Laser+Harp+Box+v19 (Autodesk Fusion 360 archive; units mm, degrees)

design "Laser Harp Box" references "US-100 Sonar Sensor with Jumper STEP"
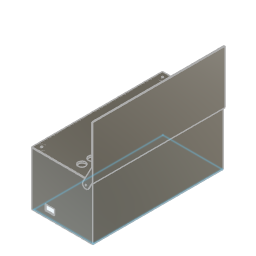
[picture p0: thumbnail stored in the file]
parameter "inner_length" = 290
parameter "inner_width" = 133
parameter "enclosure_height" = 120
parameter "screw_holder" = 9
parameter "screw_hole" = 3.8
parameter "base_height" = 13
parameter "base_plate_fastener_height" = 14.5
parameter "top_plate_fastener_height" = 14.5
parameter "top_height" = 2
parameter "wall_thickness" = 2
parameter "arduino_inputs_height" = 15
parameter "arduino_inputs_width" = 107
parameter "power_input_height" = 13
parameter "power_input_width" = 21
parameter "ultrasonic_sensor_diameter" = 16
parameter "ultrasonic_sensors_space" = 22.9
parameter "ultrasonic_space_to_side" = 22
parameter "ultrasonic_space_to_bottom" = 47
sketch "Sketch1" plane through (0, 0, 0) normal (0, 0, 1) x axis (1, 0, 0)
  line L1 (-66.5, -145) -> (66.5, -145)
  line L2 (-66.5, 145) -> (-66.5, -145)
  line L3 (66.5, 145) -> (-66.5, 145)
  line L4 (66.5, -145) -> (66.5, 145)
  line L5 (-66.5, 145) -> (66.5, -145)
  line L6 (66.5, 145) -> (-66.5, -145)
  line L7 (68.5, -147) -> (68.5, 147)
  line L8 (-68.5, -147) -> (68.5, -147)
  line L9 (-68.5, 147) -> (-68.5, -147)
  line L10 (68.5, 147) -> (-68.5, 147)
  circle C1 centre (-57.5, 136) radius 9
  circle C2 centre (-57.5, 136) radius 1.9
  circle C3 centre (-57.5, -136) radius 9
  circle C4 centre (-57.5, -136) radius 1.9
  circle C5 centre (57.5, -136) radius 9
  circle C6 centre (57.5, -136) radius 1.9
  circle C7 centre (57.5, 136) radius 9
  circle C8 centre (57.5, 136) radius 1.9
  point P6 (0, 0)
  point P1 (0, 0)
  point P4 (-66.5, 145)
  point P5 (66.5, 145)
  point P3 (-66.5, -145)
  horizontal L1
  perpendicular L1 L2
  parallel L1 L3
  parallel L2 L4
  coincident L5 P6
  coincident L6 P6
  coincident P1 P6
  tangent L2 C1
  tangent L3 C1
  concentric C1 C2
  tangent L2 C3
  tangent L1 C3
  concentric C3 C4
  tangent L1 C5
  tangent L4 C5
  concentric C5 C6
  tangent L3 C7
  tangent L4 C7
  concentric C7 C8
  dimension "d1" distance P4 P5 = 133 (= "inner_width")
  dimension "d2" distance P3 P4 = 290 (= "inner_length")
  dimension "d7" radius C1 = 9 (= "screw_holder")
  dimension "d8" diameter C2 = 3.8 (= "screw_hole")
  dimension "d11" radius C3 = 9 (= "screw_holder")
  dimension "d12" diameter C4 = 3.8 (= "screw_hole")
  dimension "d13" radius C5 = 9 (= "screw_holder")
  dimension "d14" diameter C6 = 3.8 (= "screw_hole")
  dimension "d15" radius C7 = 9 (= "screw_holder")
  dimension "d16" diameter C8 = 3.8 (= "screw_hole")
extrude "Extrude1" new body sketch "Sketch1" profile of L1 L2 L3 L4 L10 L9 L8 L7 along normal blind 120 (= "enclosure_height") bodies "Enclosure"
work_plane "WorkPlane1" AlongDistance 13 (= "base_height")
extrude "Extrude2" add sketch "Sketch1" profile of L1 L2 L3 L4 C1 C2 C3 C4 C5 C6 C7 C8 to an object from offset 13 (= "base_height")
work_plane "WorkPlane2" AlongDistance 0
sketch "Sketch3" plane through (0, 0, 120) normal (0, 0, 1) x axis (1, 0, 0)
  line L1 (57.5, 145) -> (-57.5, 145)
  line L2 (66.5, -136) -> (66.5, 136)
  line L3 (-57.5, -145) -> (57.5, -145)
  line L4 (-66.5, 136) -> (-66.5, -136)
  line L5 (-68.5, -147) -> (-68.5, 147)
  line L6 (68.5, -147) -> (-68.5, -147)
  line L7 (68.5, 147) -> (68.5, -147)
  line L8 (-68.5, 147) -> (68.5, 147)
  line L9 (-68.5, -147) -> (68.5, -147)
  line L10 (-68.5, 147) -> (-68.5, -147)
  line L11 (68.5, 147) -> (-68.5, 147)
  line L12 (68.5, -147) -> (68.5, 147)
  line L13 (-53.2574, -144.5) -> (53.2574, -144.5)
  line L14 (-66, 131.7574) -> (-66, -131.7574)
  line L15 (53.2574, 144.5) -> (-53.2574, 144.5)
  line L16 (66, -131.7574) -> (66, 131.7574)
  circle C1 centre (57.5, 136) radius 1.9
  circle C2 centre (-57.5, -136) radius 1.9
  circle C3 centre (57.5, -136) radius 1.9
  circle C4 centre (-57.5, 136) radius 1.9
  arc A1 centre (57.5, 136) radius 9 clockwise from (66.5, 136) to (57.5, 145)
  arc A2 centre (57.5, -136) radius 9 clockwise from (57.5, -145) to (66.5, -136)
  arc A3 centre (-57.5, -136) radius 9 clockwise from (-66.5, -136) to (-57.5, -145)
  arc A4 centre (-57.5, 136) radius 9 clockwise from (-57.5, 145) to (-66.5, 136)
  arc A5 centre (-57.5, -136) radius 9.5 clockwise from (-66, -131.7574) to (-53.2574, -144.5)
  arc A6 centre (-57.5, 136) radius 9.5 clockwise from (-53.2574, 144.5) to (-66, 131.7574)
  arc A7 centre (57.5, 136) radius 9.5 clockwise from (66, 131.7574) to (53.2574, 144.5)
  arc A8 centre (57.5, -136) radius 9.5 clockwise from (53.2574, -144.5) to (66, -131.7574)
  point P14 (-68.5, 147)
  point P20 (-68.5, 147)
  point P16 (68.5, -147)
  point P18 (68.5, -147)
  horizontal L9
  vertical L10
  horizontal L11
  vertical L12
  coincident P14 P20
  coincident P16 P18
  dimension "d34" = 0.5
extrude "Extrude4" new body sketch "Sketch3" along normal blind 2 (= "top_height") bodies "Lid"
extrude "Extrude5" new body sketch "Sketch3" profile of L1 A1 L2 A2 L3 A3 L4 A4 A8 A7 L15 A5 A6 L16 L14 L13 no distance stored
combine "Combine5"
extrude "Extrude6" add sketch "Sketch3" profile of A8 A7 L15 A5 A6 L16 L14 L13 no distance stored
sketch "Sketch6" plane through (0, 147, 0) normal (0, 1, 0) x axis (-1, 0, 0)
  line L1 (68.5, 0) -> (-68.5, 0)
  line L2 (68.5, 120) -> (68.5, 0)
  line L3 (-68.5, 120) -> (68.5, 120)
  line L4 (-68.5, 0) -> (-68.5, 120)
  line L5 (0, 13) -> (0, 0)
  line L6 (-53.5, 13) -> (53.5, 13)
  line L7 (-53.5, 28) -> (-53.5, 13)
  line L8 (53.5, 28) -> (-53.5, 28)
  line L9 (53.5, 13) -> (53.5, 28)
  point P1 (0, 0)
  point P6 (0, 0)
  point P7 (0, 13)
  point P8 (53.5, 13)
  point P9 (-53.5, 13)
  point P11 (53.5, 28)
  coincident P1 P6
  perpendicular L1 L5
  horizontal L6
  vertical L7
  horizontal L8
  vertical L9
  midpoint P7 L6
  dimension "d46" distance P6 P7 = 13 (= "base_height")
  dimension "d47" distance P8 P9 = 107 (= "arduino_inputs_width")
  dimension "d48" distance P8 P11 = 15 (= "arduino_inputs_height")
extrude "Extrude7" cut sketch "Sketch6" profile of L6 L7 L8 L9 against normal blind 30
sketch "Sketch7" plane through (0, -147, 0) normal (0, -1, 0) x axis (1, 0, 0)
  line L1 (68.5, 0) -> (-68.5, 0)
  line L2 (68.5, 120) -> (68.5, 0)
  line L3 (-68.5, 120) -> (68.5, 120)
  line L4 (-68.5, 0) -> (-68.5, 120)
  line L5 (-38.5, 13) -> (-68.5, 13)
  line L6 (-38.5, 0) -> (-38.5, 13)
  line L7 (-17.5, 13) -> (-38.5, 13)
  line L8 (-17.5, 26) -> (-17.5, 13)
  line L9 (-38.5, 26) -> (-17.5, 26)
  line L10 (-38.5, 13) -> (-38.5, 26)
  point P6 (-68.5, 13)
  point P7 (-38.5, 13)
  point P8 (-38.5, 0)
  point P9 (-17.5, 13)
  point P11 (-38.5, 26)
  coincident L4 P6
  perpendicular L4 L5
  perpendicular L1 L6
  horizontal L7
  vertical L8
  horizontal L9
  vertical L10
  dimension "d54" distance P6 P7 = 30
  dimension "d55" distance P7 P8 = 13 (= "base_height")
  dimension "d56" distance P7 P9 = 21 (= "power_input_width")
  dimension "d57" distance P7 P11 = 13 (= "power_input_height")
extrude "Extrude8" cut sketch "Sketch7" profile of L7 L8 L9 L10 against normal blind 15
sketch "Sketch8" plane through (0, 0, 122) normal (0, 0, 1) x axis (-1, 0, 0)
  line L1 (68.5, -147) -> (-68.5, -147)
  line L2 (68.5, 147) -> (68.5, -147)
  line L3 (-68.5, 147) -> (68.5, 147)
  line L4 (-68.5, -147) -> (-68.5, 147)
  line L5 (21.5, -45) -> (11.5, -45)
  line L6 (21.5, 45) -> (21.5, -45)
  line L7 (11.5, 45) -> (21.5, 45)
  line L8 (11.5, -45) -> (11.5, 45)
  line L9 (21.5, 45) -> (11.5, -45)
  line L10 (11.5, 45) -> (21.5, -45)
  line L11 (68.5, -147) -> (68.5, 147)
  line L12 (-68.5, -147) -> (68.5, -147)
  line L13 (-68.5, 147) -> (-68.5, -147)
  line L14 (-68.5, 0) -> (0, 0)
  line L15 (-4.8, 147) -> (-4.8, -147)
  circle C1 centre (57.5, -136) radius 1.9
  circle C2 centre (-57.5, -136) radius 1.9
  circle C3 centre (57.5, 136) radius 1.9
  circle C4 centre (-57.5, 136) radius 1.9
  circle C5 centre (-21.5, -102.1) radius 8
  circle C6 centre (-21.5, -125) radius 8
  circle C7 centre (-21.5, 125) radius 8
  circle C8 centre (-21.5, 102.1) radius 8
  circle C9 centre (-4.8, -82) radius 0.6
  circle C10 centre (-4.8, -79.4) radius 0.6
  circle C11 centre (-4.8, -32.4) radius 0.6
  circle C12 centre (-4.8, -29.8) radius 0.6
  circle C13 centre (-4.8, 32.4) radius 0.6
  circle C14 centre (-4.8, 29.8) radius 0.6
  circle C15 centre (-4.8, 82) radius 0.6
  circle C16 centre (-4.8, 79.4) radius 0.6
  point P14 (16.5, 0)
  point P1 (0, 0)
  point P21 (0, 0)
  point P22 (-68.5, 0)
  point P25 (-4.8, -147)
  point P26 (-4.8, 147)
  point P27 (-4.8, -82)
  point P28 (-4.8, -79.4)
  point P30 (-4.8, -32.4)
  point P29 (-4.8, -29.8)
  point P12 (21.5, 45)
  point P13 (11.5, 45)
  point P11 (21.5, -45)
  point P17 (-21.5, -102.1)
  point P18 (-21.5, -125)
  horizontal L5
  perpendicular L5 L6
  parallel L5 L7
  parallel L6 L8
  coincident L9 P14
  coincident L10 P14
  coincident P1 P21
  midpoint L13 P22
  symmetric C5 L14 C8
  symmetric C6 L14 C7
  coincident L1 P25
  coincident L3 P26
  perpendicular L3 L15
  coincident L15 P27
  coincident L15 P28
  coincident L15 P30
  coincident L15 P29
  symmetric L14 C9 C15
  symmetric L14 C10 C16
  symmetric L14 C11 C13
  symmetric L14 C12 C14
  dimension "d60" distance P12 P13 = 10
  dimension "d61" distance P11 P12 = 90
  dimension "d62" distance L6 L11 = 47
  dimension "d63" diameter C5 = 16 (= "ultrasonic_sensor_diameter")
  dimension "d64" diameter C6 = 16 (= "ultrasonic_sensor_diameter")
  dimension "d65" distance P17 P18 = 22.9 (= "ultrasonic_sensors_space")
  dimension "d66" distance P18 L12 = 22 (= "ultrasonic_space_to_side")
  dimension "d67" distance P17 L13 = 47 (= "ultrasonic_space_to_bottom")
  dimension "d88" distance L8 L15 = 16.3
  dimension "d89" diameter C9 = 1.2
  dimension "d90" diameter C10 = 1.2
  dimension "d91" distance P27 P28 = 2.6
  dimension "d92" distance P25 P27 = 65
  dimension "d93" diameter C11 = 1.2
  dimension "d94" diameter C12 = 1.2
  dimension "d95" distance P29 P30 = 2.6
  dimension "d96" distance P28 P30 = 47
extrude "Extrude9" cut sketch "Sketch8" profile of C1 C2 C3 C4 L5 L6 L7 L8 against normal blind 20
sketch "Sketch9" plane through (68.5, 0, 0) normal (1, 0, 0) x axis (0, 1, 0)
  line L1 (147, 0) -> (-147, 0)
  line L2 (147, 120) -> (147, 0)
  line L3 (-147, 120) -> (147, 120)
  line L4 (-147, 0) -> (-147, 120)
  line L5 (147, 120) -> (-147, 120)
  line L6 (147, 240) -> (147, 120)
  line L7 (-147, 240) -> (147, 240)
  line L8 (-147, 120) -> (-147, 240)
  point P5 (-147, 120)
  point P6 (-147, 120)
  point P9 (-147, 240)
  horizontal L5
  vertical L6
  horizontal L7
  vertical L8
  coincident P5 P6
  collinear L2 L6
  dimension "d74" distance P6 P9 = 120
extrude "Extrude10" new body sketch "Sketch9" profile of L3 L5 L6 L7 L8 along normal blind 2 bodies "Mirror Holder"
sketch "Sketch10" plane through (0, 147, 0) normal (0, 1, 0) x axis (-1, 0, 0)
  line L1 (-68.5, 240) -> (-68.5, 120)
  line L2 (-70.5, 240) -> (-68.5, 240)
  line L3 (-70.5, 120) -> (-70.5, 240)
  line L4 (-68.5, 120) -> (-70.5, 120)
  line L5 (-60.6488, 105.0663) -> (-68.5, 120)
  line L6 (-68.5, 151.6386) -> (-47.9407, 112.5332)
  line L7 (-68.5, 240) -> (-70.5, 240)
  line L8 (-68.5, 120) -> (-68.5, 240)
  line L9 (-70.5, 120) -> (-68.5, 120)
  line L10 (-70.5, 240) -> (-70.5, 120)
  circle C1 centre (-55, 110) radius 7.5
  circle C2 centre (-55, 110) radius 1.5
  point P2 (-68.5, 120)
  point P7 (-68.5, 120)
  point P8 (-60.6488, 105.0663)
  point P9 (-47.9407, 112.5332)
  point P10 (-68.5, 151.6386)
  point P4 (-70.5, 240)
  point P12 (-70.5, 240)
  coincident P2 P7
  coincident C1 P8
  coincident C1 P9
  coincident L1 P10
  parallel L5 L6
  concentric C1 C2
  horizontal L7
  vertical L8
  horizontal L9
  vertical L10
  coincident P4 P12
  dimension "d77" diameter C1 = 15
  dimension "d78" diameter C2 = 3
extrude "Extrude11" new body sketch "Sketch10" along normal blind 2
mirror "Mirror1" mirrorStitchTolerance 0.1
combine "Combine6"
offset_faces "OffsetFaces1" distance -0.4
offset_faces "OffsetFaces2" distance -0.4
component_insert "Component Insert"
combine "Combine7"
offset_faces "OffsetFaces3" distance -0.4
mirror "Mirror2" mirrorStitchTolerance 0.1
extrude "Extrude12" cut sketch "Sketch8" profile of C9 C10 C11 C12 C13 C14 C15 C16 against normal blind 4
hole "Hole1" HoleDepth 10 HoleDiameter 3 TipAngle 118
hole "Hole2" HoleDepth 10 HoleDiameter 3 TipAngle 118
canvas "Canvas5" bodies "Lid"
sketch "Sketch11" plane through (0, 0, 0) normal (0, 0, 1) x axis (1, 0, 0)
  line L1 (-65.867, 145.4698) -> (67.133, 145.4698)
  line L2 (-65.867, -144.5302) -> (-65.867, 145.4698)
  line L3 (67.133, -144.5302) -> (-65.867, -144.5302)
  line L4 (67.133, 145.4698) -> (67.133, -144.5302)
  point P2 (67.133, 145.4698)
  point P3 (-65.867, 145.4698)
  point P5 (67.133, -144.5302)
  horizontal L1
  vertical L2
  horizontal L3
  vertical L4
  dimension "d105" distance P2 P3 = 133
  dimension "d106" distance P2 P5 = 290
named bodies: "Enclosure", "Lid", "Mirror Holder"

design "US-100 Sonar Sensor with Jumper STEP"
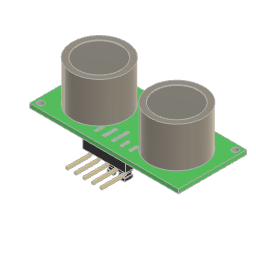
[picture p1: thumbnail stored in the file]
description: STEP AP214
part number: US-100 Sonar Sensor with Jumper STEP
base_feature "Base Feature"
